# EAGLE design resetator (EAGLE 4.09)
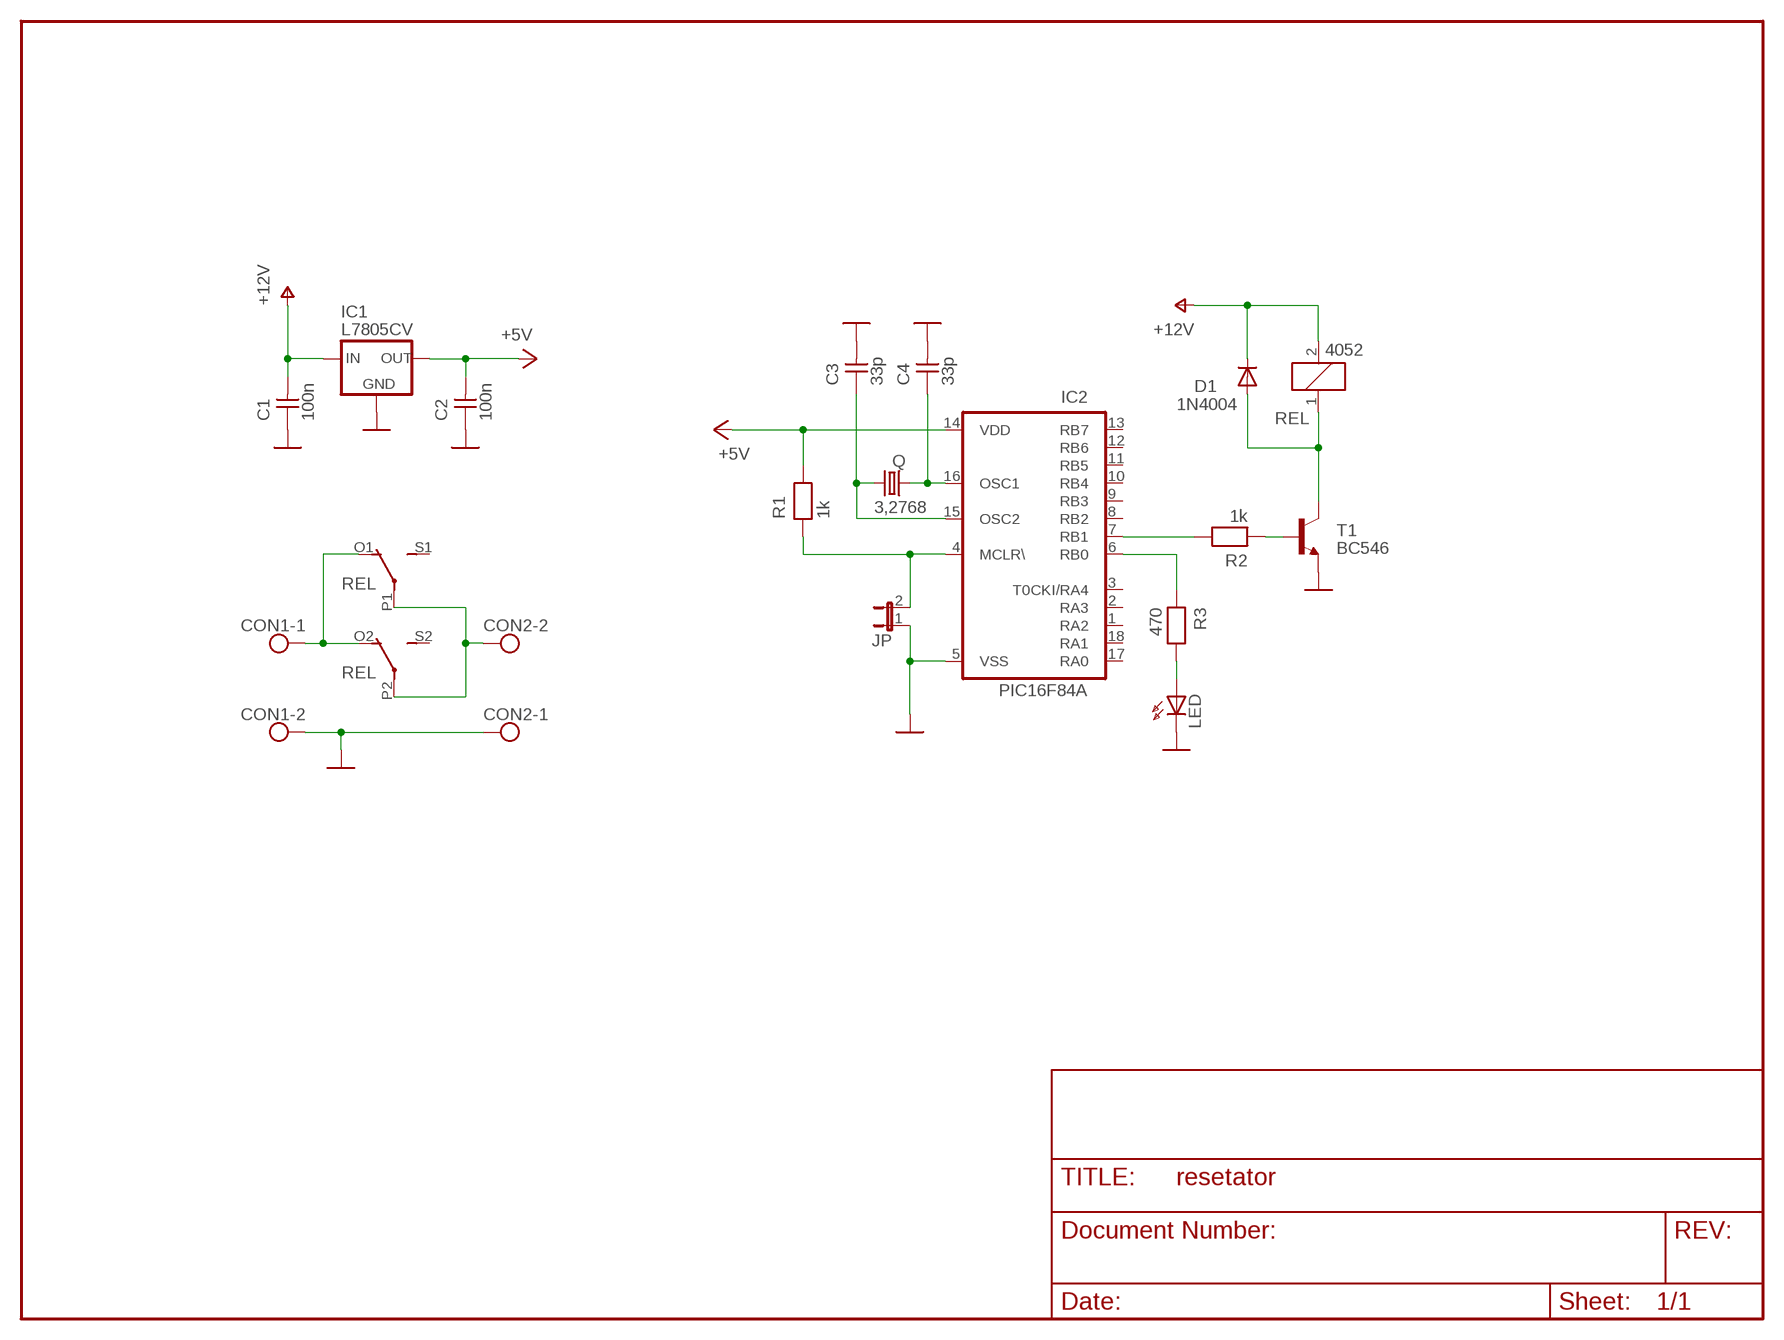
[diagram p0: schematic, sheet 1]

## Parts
C1  100n  CAPNP-2,5  [C-2,5]
C2  100n  CAPNP-2,5  [C-2,5]
C3  33p  CAPNP-2,5  [C-2,5]
C4  33p  CAPNP-2,5  [C-2,5]
CON1  AK300/2  [AK300/2]
CON2  AK300/2  [AK300/2]
D1  1N4004  [DO41-10]
IC1  L7805CV  78XXS  [78XXS]
IC2  PIC16F84A  PIC16F84AP  [DIL18]
JP  JP1E  [JP1]
LED  LED3MM  [LED3MM]
Q  3,2768  CRYTALHC49U-V  [HC49U-V]
R1  1k  RESEU-5  [R-5]
R2  1k  RESEU-5  [R-5]
R3  470  RESEU-5  [R-5]
REL  4052  [F4052]
T1  BC546  BC237  [TO92]

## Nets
+5V: C2.2 IC1.OUT IC2.14(VDD) R1.2
GND: C1.1 C2.1 C3.2 C4.2 CON1.2 CON2.1 IC1.GND IC2.5(VSS) JP.1 LED.K(C) T1.1(E)
MCLR\: IC2.4(MCLR\) JP.2 R1.1
N$1: R2.1 T1.2(B)
N$2: LED.A R3.2
N$3: D1.A REL.1 T1.3(C)
OSC1: C4.1 IC2.16(OSC1) Q.1
OSC2: C3.1 IC2.15(OSC2) Q.2
RB0: IC2.6(RB0) R3.1
RB1: IC2.7(RB1) R2.2
V+: C1.2 CON1.1 D1.C IC1.IN REL.2 REL.O1(2:O) REL.O2(3:O) ; supply symbol labelled +12V
VS+: CON2.2 REL.P1(2:P) REL.P2(3:P)
Unconnected: IC2.1(RA2) IC2.2(RA3) IC2.3(T0CKI/RA4) IC2.8(RB2) IC2.9(RB3) IC2.10(RB4) IC2.11(RB5) IC2.12(RB6) IC2.13(RB7) IC2.17(RA0) IC2.18(RA1) REL.S1(2:S) REL.S2(3:S)

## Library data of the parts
C1-C4 = discrete:CAPNP-2,5
CON1 CON2 = con-ptr500:AK300/2: CONNECTOR
D1 = diode:1N4004: DIODE
IC1 = v-reg:78XXS: VOLTAGE REGULATOR
IC2 = microchip:PIC16F8*: MICROCONTROLLER 8-Bit PIC16F8X Family - CMOS Flash/EEPROM Pin Compatible : PIC16F83, PIC16CR83, PIC16F84A, PIC16CR84 see also PIC16C*
JP = jumper:JP1E: JUMPER
LED = led:LED: LED
Q = crystal:CRYTAL: CRYSTAL
R1-R3 = discrete:RESEU-5
REL = relay:4052: RELAY 2 x switch, Finder
T1 = transistor-npn:BC237: NPN Transistor

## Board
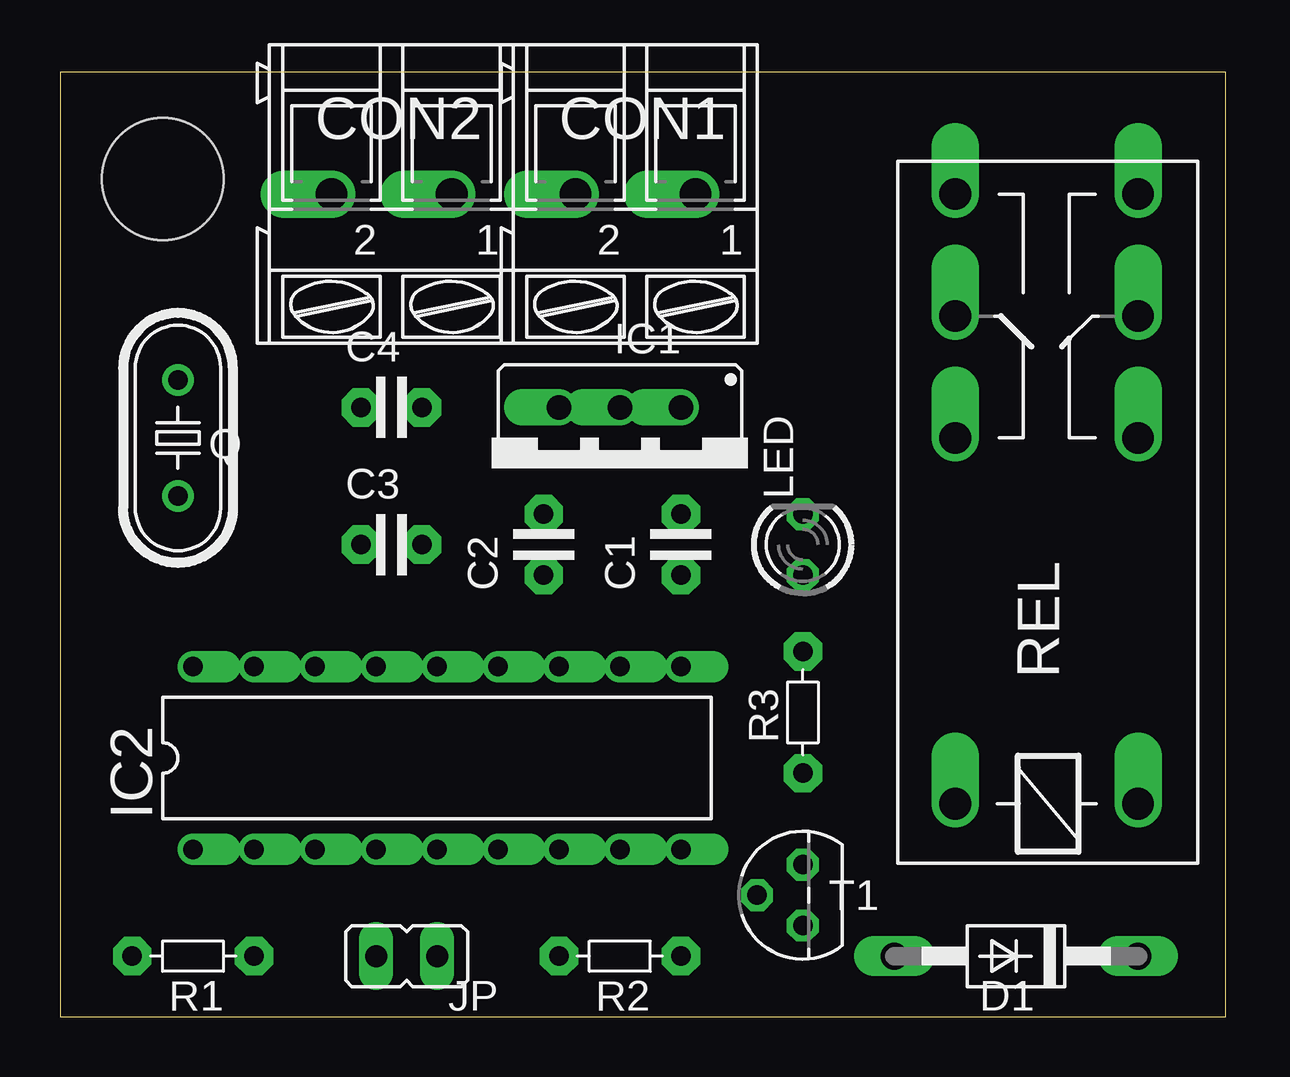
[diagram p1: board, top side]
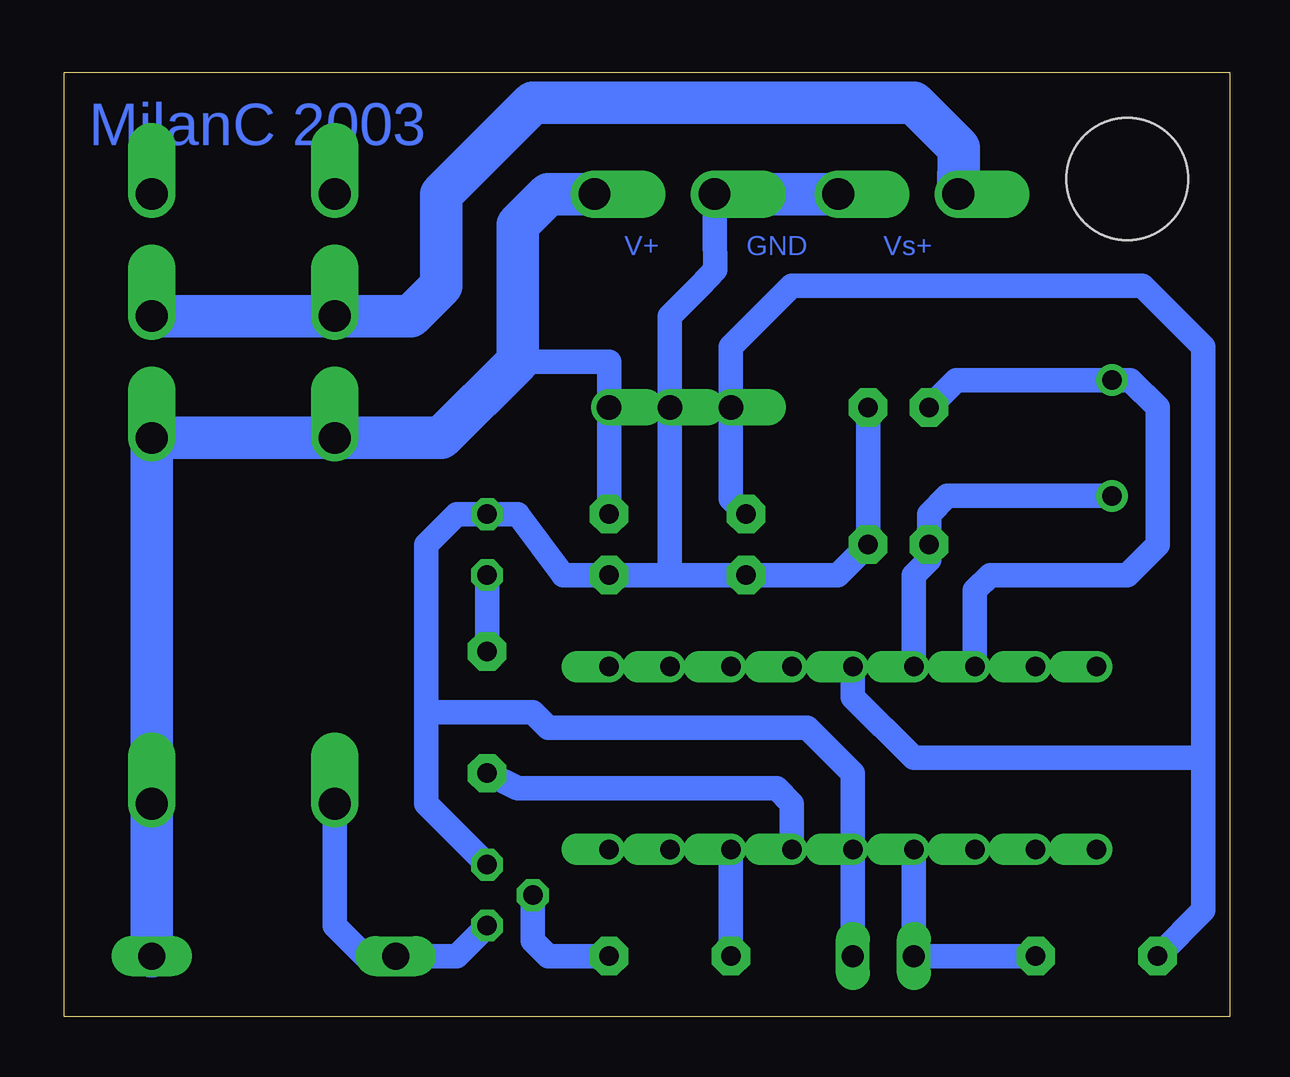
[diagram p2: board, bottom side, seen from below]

Size 48.56 x 39.36 mm. Coordinates in mm from the lower left corner, seen from the top.
Outline: 0,0 48.56,0 48.56,39.36 0,39.36 0,0
Copper layers used: Bottom
Holes 5.08 mm at 4.28,34.92

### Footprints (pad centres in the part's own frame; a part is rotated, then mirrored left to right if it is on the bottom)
C-2,5 = drill 0.813 pad 1.6 octagon: 1 -1.27,0; 2 1.27,0
AK300/2 = drill 1.321 offset: 1 -2.515,0; 2 2.489,0
DO41-10 = drill 1.118 long: A 5.08,0; C -5.08,0
78XXS = drill 1.016 offset: GND 0,-2.54; IN -2.54,-2.54; OUT 2.54,-2.54
DIL18 = drill 0.813 offset: 1 -10.16,-3.81; 2 -7.62,-3.81; 3 -5.08,-3.81; 4 -2.54,-3.81; 5 0,-3.81; 6 2.54,-3.81; 7 5.08,-3.81; 8 7.62,-3.81; 9 10.16,-3.81; 10 10.16,3.81; 11 7.62,3.81; 12 5.08,3.81; 13 2.54,3.81; 14 0,3.81; 15 -2.54,3.81; 16 -5.08,3.81; 17 -7.62,3.81; 18 -10.16,3.81
JP1 = drill 0.914 long: 1 0,-1.27; 2 0,1.27
LED3MM = drill 0.813 octagon: A -1.27,0; K 1.27,0
HC49U-V = drill 0.813 round: 1 -2.413,0; 2 2.413,0
R-5 = drill 0.813 pad 1.6 octagon: 1 -2.54,0; 2 2.54,0
F4052 = drill 1.321 offset: 1 -3.81,3.81; 2 -3.81,-3.81; O1 11.43,-3.81; O2 11.43,3.81; P1 16.51,-3.81; P2 16.51,3.81; S1 21.59,-3.81; S2 21.59,3.81
TO92 = drill 0.813 octagon: 1 1.27,0; 2 0,1.905; 3 -1.27,0

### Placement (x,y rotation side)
C1  25.87,19.68 90 top
C2  20.15,19.68 90 top
C3  13.81,19.68 0 top
C4  13.81,25.39 0 top
CON1  23.96,34.28 180 top
CON2  13.81,34.28 180 top
D1  39.84,2.54 180 top
IC1  23.33,22.86 180 top
IC2  15.71,10.79 0 top
JP  14.44,2.54 90 top
LED  30.95,19.68 90 top
Q  4.92,24.12 270 top
R1  5.55,2.54 180 top
R2  23.33,2.54 180 top
R3  30.95,12.69 90 top
REL  41.11,12.69 90 top
T1  30.95,5.08 90 top

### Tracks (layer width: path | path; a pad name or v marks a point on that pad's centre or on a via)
+5V
  Bottom 1.016: 1.1,10.79 1.1,4.44 R1.2 | 1.1,10.79 1.1,27.94 3.64,30.48 18.25,30.48 20.79,27.94 IC1.OUT 20.79,21.59 C2.2 | IC2.14 15.71,13.33 13.17,10.79 1.1,10.79
GND
  Bottom 1.016: 23.33,18.41 IC1.GND 23.33,29.21 22.06,30.48 21.45,31.14 CON1.2 | 23.33,18.41 C2.1 16.34,18.41 C3.2 C4.2 | 23.33,18.41 C1.1 27.77,18.41 29.68,20.95 LED.K 32.22,20.95 33.49,19.68 33.49,12.69 | T1.1 33.49,8.88 33.49,12.69 | 33.49,12.69 29.04,12.69 28.41,12.06 17.61,12.06 15.71,10.15 IC2.5 JP.1
  Bottom 1.778: CON1.2 CON2.1
MCLR\
  Bottom 1.016: R1.1 JP.2 IC2.4
N$1
  Bottom 1.016: T1.2 29.04,3.17 28.41,2.54 R2.1
N$2
  Bottom 1.016: R3.2 LED.A
N$3
  Bottom 1.016: REL.1 37.3,3.81 36.03,2.54 D1.A 32.22,2.54 T1.3
OSC1
  Bottom 1.016: IC2.16 10.63,17.78 10,18.41 4.28,18.41 3.01,19.68 3.01,25.39 4.15,26.54 Q.1 11.39,26.54 C4.1
OSC2
  Bottom 1.016: IC2.15 13.17,18.41 12.54,19.05 C3.1 12.54,20.95 11.77,21.71 Q.2
RB0
  Bottom 1.016: IC2.6 18.25,8.88 18.88,9.52 29.68,9.52 R3.1
RB1
  Bottom 1.016: R2.2 IC2.7
V+
  Bottom 1.016: C1.2 IC1.IN 25.87,27.3 29.68,27.3
  Bottom 1.27: REL.O1 REL.2 D1.C
  Bottom 1.778: CON1.1 28.41,34.28 29.68,33.02 29.68,27.3 32.85,24.12 REL.O2 REL.O1 REL.2 D1.C
VS+
  Bottom 1.778: CON2.2 11.29,36.21 13.17,38.09 29.04,38.09 32.85,34.28 32.85,30.48 34.12,29.21 REL.P2 REL.P1

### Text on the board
Bottom: MilanC 2003 | Vs+ | GND | V+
